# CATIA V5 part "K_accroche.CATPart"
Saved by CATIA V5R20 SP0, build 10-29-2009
Part number: accroche
Bounding box of the stored display mesh (mm): x 0 to 19, y 35.401 to 50.401, z 61.418 to 76.418
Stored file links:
  G:\Khaled_CFAO_2011\ST2M\ST2M_GR2\gcausse\Khaled\CAD_ThinkMotion\K_accroche.CATPart
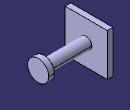
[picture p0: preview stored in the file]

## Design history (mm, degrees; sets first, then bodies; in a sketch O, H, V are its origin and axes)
Set1
  Sketch1 on yz-plane, origin (0, 0, 0), H (0, 1, 0), V (0, 0, 1)
    line L1 (35.4013, 76.4175) -> (50.4013, 76.4175)
    line L2 (50.4013, 76.4175) -> (50.4013, 61.4175)
    line L3 (50.4013, 61.4175) -> (35.4013, 61.4175)
    line L4 (35.4013, 61.4175) -> (35.4013, 76.4175)
    length L2 = 15
    length L1 = 15
    horizontal: L1 H, L3 H
    vertical: L2 V, L4 V
Body1 (main body)
  Pad1: profile Sketch1, direction (1, 0, 0), length 2
  Sketch2 on end face of Pad1, origin (2, 0, 0), H (0, 1, 0), V (0, 0, 1)
    circle A1 centre (42.9013, 68.9175) radius 2
    point P1 (42.9013, 68.9175)
    reference projected line E1 (52.9162, 76.4175) -> (32.9162, 76.4175) from edge [face of Pad1 from Sketch1.L1 | end face of Pad1]
    reference projected line E2 (32.9162, 61.4175) -> (52.9162, 61.4175) from edge [face of Pad1 from Sketch1.L3 | end face of Pad1]
    reference projected line E3 (50.4013, 61.3887) -> (50.4013, 76.3887) from edge [face of Pad1 from Sketch1.L2 | end face of Pad1]
    reference projected line E4 (35.4013, 76.3887) -> (35.4013, 61.3887) from edge [face of Pad1 from Sketch1.L4 | end face of Pad1]
    equidistance: E1 E2 P1, E3 E4 P1
  Pad2: profile Sketch2, direction (1, 0, 0), length 15
  Sketch3 on end face of Pad2, origin (17, 0, 0), H (0, 1, 0), V (0, 0, 1)
    circle A1 centre (42.9013, 68.9175) radius 3.7298
    point P1 (42.9013, 68.9175)
    reference projected circle E1 centre (42.9013, 68.9175) radius 2 from edge [face of Pad2 from Sketch2.A1 | end face of Pad2]
    concentricity: P1 E1
  Pad3: profile Sketch3, direction (1, 0, 0), length 2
